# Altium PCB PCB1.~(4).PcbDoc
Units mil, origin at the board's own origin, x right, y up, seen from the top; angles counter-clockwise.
Board outline 6000 x 4000 mil, 2 copper layers (Top Layer, Bottom Layer); 3 components, 4 nets, 37 pads, 0 vias.
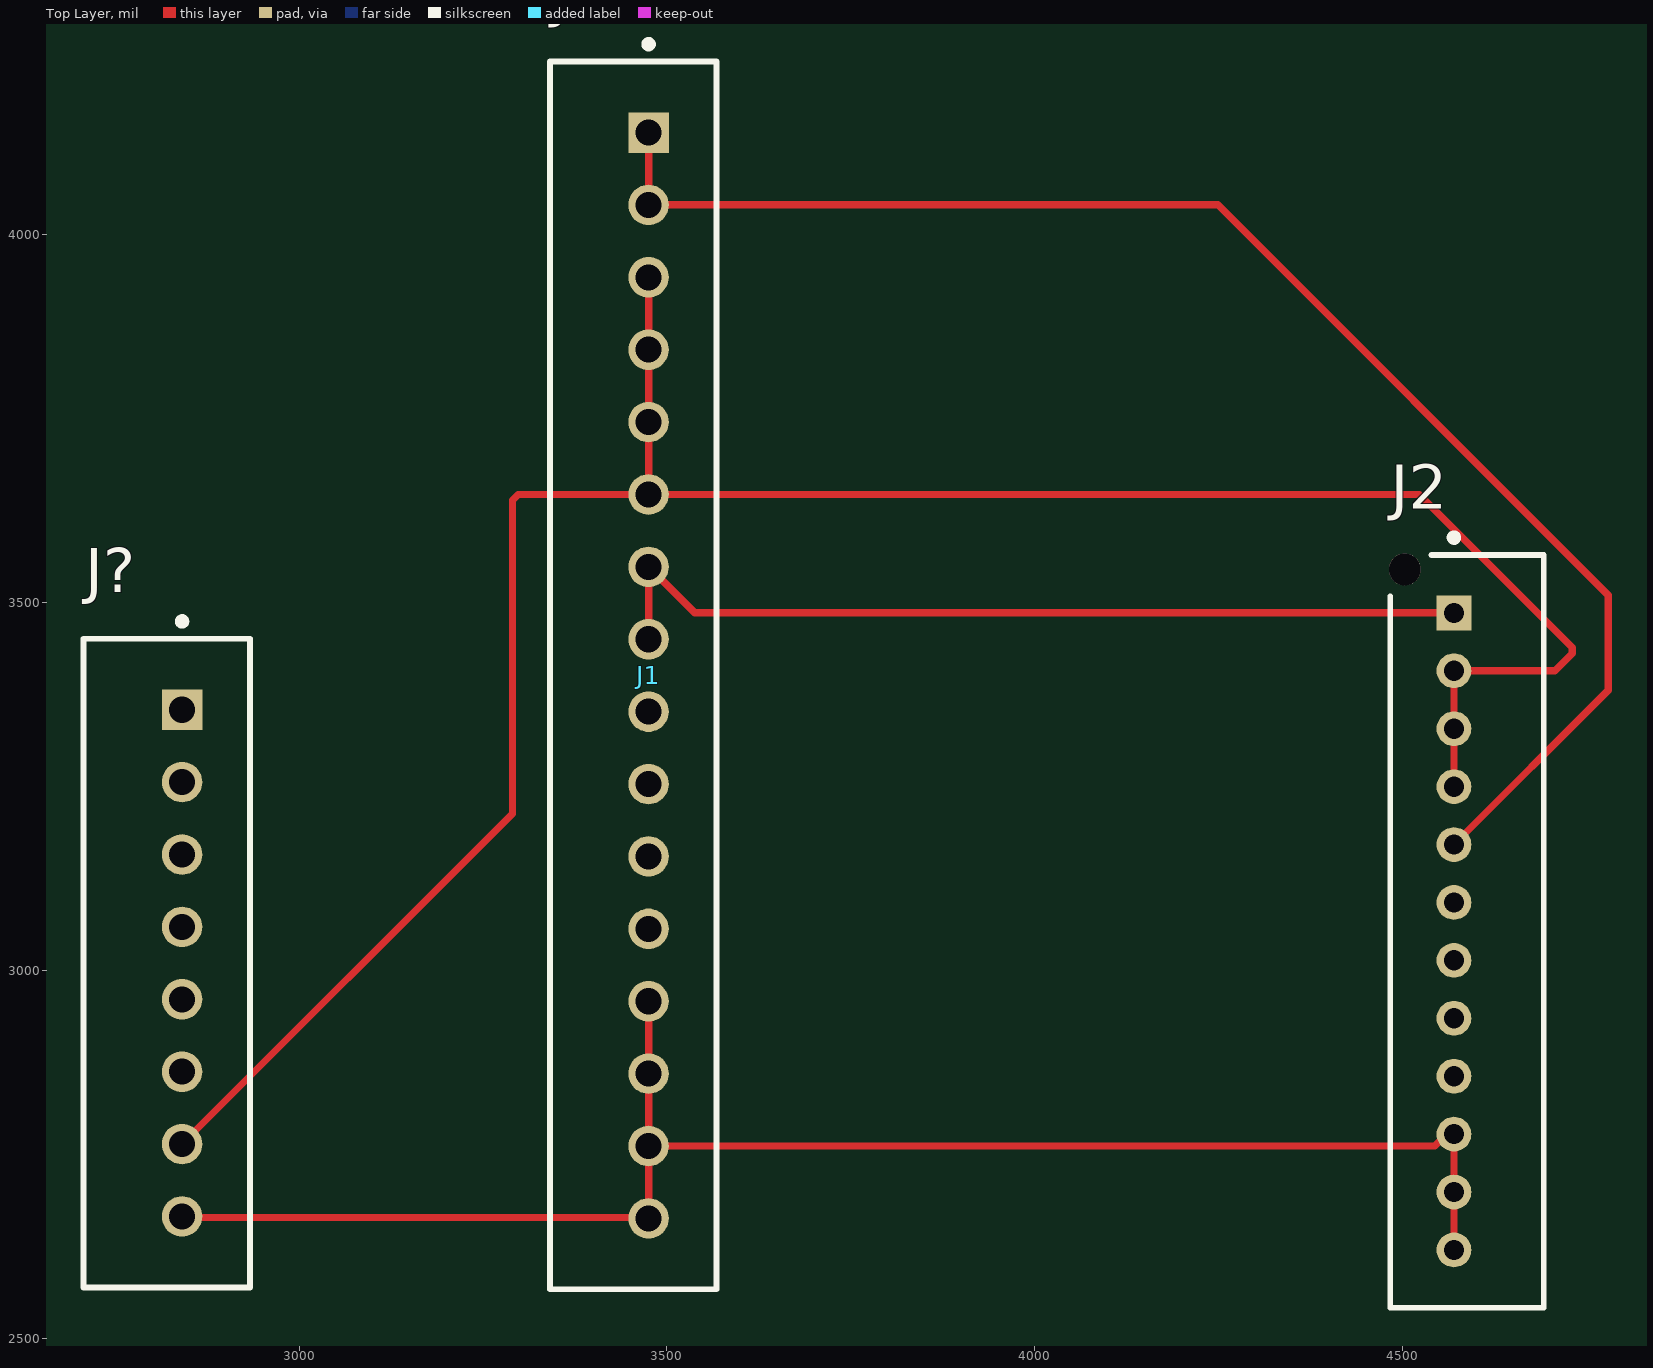
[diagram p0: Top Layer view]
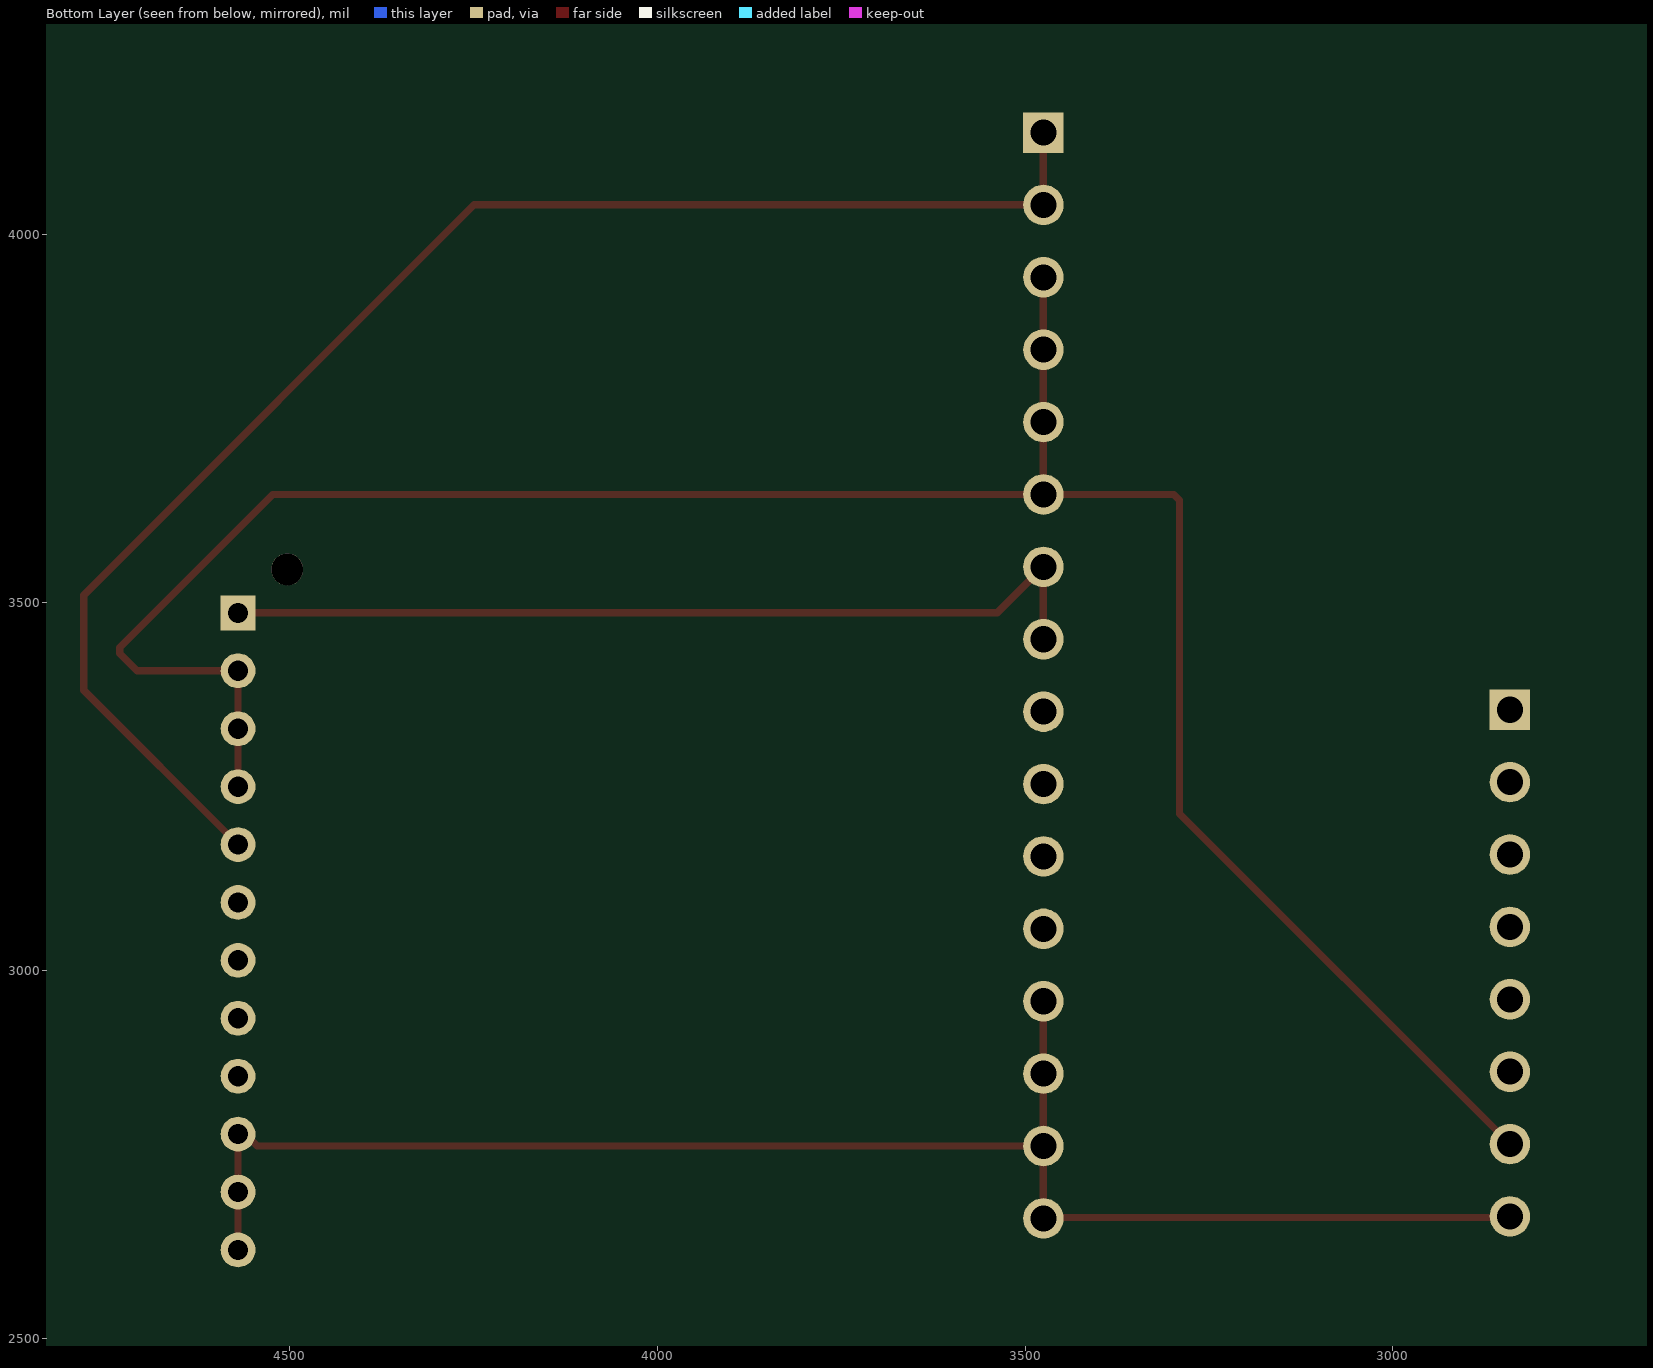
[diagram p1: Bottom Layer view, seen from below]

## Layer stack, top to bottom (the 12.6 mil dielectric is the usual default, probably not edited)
Top Solder: solder mask 0.4, Solder Resist, Dk 3.5
Top Layer: signal copper 1.4
Dielectric 1: dielectric 12.6, FR-4, Dk 4.8
Bottom Layer: signal copper 1.4
Bottom Solder: solder mask 0.4, Solder Resist, Dk 3.5

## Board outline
1000,1000 7000,1000 7000,5000 1000,5000

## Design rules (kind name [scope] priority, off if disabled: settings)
Clearance [All] p1: gap=10 ignorepadtopadclearanceinfootprint=FALSE
PolygonConnect [All] p1: connectstyle=Relief reliefconductorwidth=10 reliefentries=4 polygonreliefangle="90 Angle" airgapwidth=10
RoutingVias [All] p1: holewidth=28 width=50 viastyle="Through Hole" minholewidth=28 minwidth=50 maxholewidth=28 maxwidth=50
SolderMaskExpansion [All] p1: expansion=0 istentingtop=FALSE
SupplyNets "Schematic Supply Nets" [InNet('GND')] p1: voltage=0.000
Width [All] p1: maxlimit=10 minlimit=10 preferedwidth=10
30 further rules are at their usual default settings.

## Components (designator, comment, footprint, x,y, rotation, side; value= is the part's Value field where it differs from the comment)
J1 "B16B-XH-A(LF)(SN)" FP-B16B-XH-A_LF_SN-MFG 3454.33,3401.06 r90 top
J2 "B12B-PASK-1(LF)(SN)" FP-B12B-PASK-1_LF_SN-MFG 4587.72,3053.07 r90 top
J? "B8B-XH-A(LF)(SN)" FP-B8B-XH-A_LF_SN-MFG 2820,3010 r90 top

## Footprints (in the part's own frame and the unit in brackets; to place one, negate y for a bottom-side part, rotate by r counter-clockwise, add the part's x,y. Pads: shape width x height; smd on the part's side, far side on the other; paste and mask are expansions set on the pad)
FP-B8B-XH-A_LF_SN-MFG [mm]
  rect 1.4x1.4 hole 0.9 paste-2539.97 mask+0: 1(8.75,-0.525)
  round 1.4 hole 0.9 paste-2539.97 mask+0: 2(6.25,-0.525) 3(3.75,-0.525) 4(1.25,-0.525) 5(-1.25,-0.525) 6(-3.75,-0.525) 7(-6.25,-0.525) 8(-8.75,-0.525)
  silkscreen extent -11.2,-2.88 11.92,2.88, body extent -11.3,-2.98 11.3,2.98, height 0.25
FP-B12B-PASK-1_LF_SN-MFG [mm]
  rect 1.2x1.2 hole 0.7 paste-2539.97 mask+0: 1(11,0.45)
  round 1.2 hole 0.7 paste-2539.97 mask+0: 2(9,0.45) 3(7,0.45) 4(5,0.45) 5(3,0.45) 6(1,0.45) 7(-1,0.45) 8(-3,0.45) 9(-5,0.45) 10(-7,0.45) 11(-9,0.45) 12(-11,0.45)
  round 1.1 hole 1.1 unplated paste-2539.97 mask+0: ""(12.5,2.15)
  silkscreen extent -13,-2.65 13.72,2.65, body extent -13.1,-2.75 13.15,2.8, height 0.25
FP-B16B-XH-A_LF_SN-MFG [mm]
  rect 1.4x1.4 hole 0.9 paste-2539.97 mask+0: 1(18.75,-0.525)
  round 1.4 hole 0.9 paste-2539.97 mask+0: 2(16.25,-0.525) 3(13.75,-0.525) 4(11.25,-0.525) 5(8.75,-0.525) 6(6.25,-0.525) 7(3.75,-0.525) 8(1.25,-0.525) 9(-1.25,-0.525) 10(-3.75,-0.525) 11(-6.25,-0.525) 12(-8.75,-0.525) 13(-11.25,-0.525) 14(-13.75,-0.525) 15(-16.25,-0.525) 16(-18.75,-0.525)
  silkscreen extent -21.2,-2.88 21.92,2.88, body extent -21.3,-2.98 21.3,2.98, height 0.25

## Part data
J1: library part CMP-17439-000590-1, "CONN HEADER VERT 16POS 2.5MM", Color=Natural, Contact Resistance=20mR, Housing Color=White, Max Current Rating=3A, Max Operating Temperature=85°C, Max Voltage Rating (AC)=250V, Min Operating Temperature=-25°C, Package Quantity=200
J2: library part CMP-17439-000523-1, "CONN HEADER VERT 12POS 2MM", Color=Natural, Current Rating=3A, Flammability Rating="UL94 V-0", Housing Color=White, Voltage Rating=250V
J?: library part CMP-17438-000015-1, "CONN HEADER VERT 8POS 2.5MM", Color=Natural, Contact Resistance=20mR, Current Rating=3A, Housing Color=White, Insulation Resistance=1GR, Max Operating Temperature=85°C, Max Voltage Rating (AC)=250V, Min Operating Temperature=-25°C

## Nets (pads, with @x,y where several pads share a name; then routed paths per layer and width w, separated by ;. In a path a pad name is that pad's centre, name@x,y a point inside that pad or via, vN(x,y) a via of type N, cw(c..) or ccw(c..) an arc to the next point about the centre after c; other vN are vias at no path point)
GND: J1.13 J1.14 J1.15 J1.16 J2.10 J2.11 J2.12 J?.8 | length 2189.9
  Top Layer w10: J?.8 2841.99,2664.19 3473.68,2664.19 J1.16 J1.15 ; J1.13 J1.14 J1.15 ; J2.12 J2.11 J2.10 4559.92,2777.48 4543.74,2761.3 J1.15
NetJ1_1: J1.1 J1.2 J2.5 | length 2049.1
  Top Layer w10: J1.1 J1.2 4249.17,4040.83 4780,3510 4780,3381.18 J2.5
NetJ1_3: J1.3 J1.4 J1.5 J1.6 J2.2 J2.3 J2.4 J?.7 | length 3223.3
  Top Layer w10: J?.7 3290,3213.27 3290,3639.14 3297.98,3647.13 J1.6 ; J1.3 J1.4 J1.5 J1.6 ; J2.4 J2.3 J2.2 4707.4,3407.4 4730.86,3430.86 4730.86,3439.14 4522.87,3647.13 J1.6
NetJ1_7: J1.7 J1.8 J2.1 | length 1219.3
  Top Layer w10: J1.8 J1.7 3537.56,3486.14 J2.1
pads on no net: J1.9 J1.10 J1.11 J1.12 J2. J2.6 J2.7 J2.8 J2.9 J?.1 J?.2 J?.3 J?.4 J?.5 J?.6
